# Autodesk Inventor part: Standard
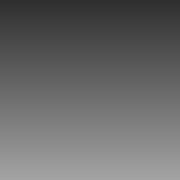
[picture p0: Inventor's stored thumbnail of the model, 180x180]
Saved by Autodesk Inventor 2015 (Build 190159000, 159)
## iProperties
Created: 2005-05
Part Number: Standard
Document SubType Name: Modeling
Designer: JWe
Density: 1 g/cm^3
Material: Generic
Appearance: Default
Author: JWe
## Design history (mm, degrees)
